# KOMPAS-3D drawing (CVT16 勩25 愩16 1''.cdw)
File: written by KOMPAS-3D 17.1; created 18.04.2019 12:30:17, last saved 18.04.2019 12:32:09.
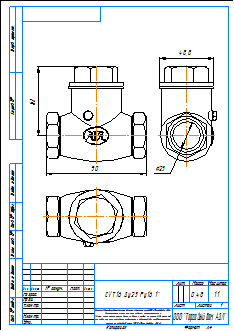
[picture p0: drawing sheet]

Sheet 1: A4, portrait

Title block, sheet 1: name: CVT16 Ду25 Ру16 1''; material: Внимание! Данный продукт является объектом авторского права ООО «Торговый Дом АДЛ». / Запрещается изменение, копирование, распространение / (в том числе путем копирования на другие сайты и ресурсы в Интернете) / или любое иное использование информации и объектов без предварительного / согласия правообладателя (ООО «Торговый Дом АДЛ»).; mass: 0,48; sheets: 1; organisation: ООО "Торговый дом АДЛ"; sheet format: A4

Views: Вид 1, Проекционный вид 2, Проекционный вид 3
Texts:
  user
Dimensions and other numbers on the sheet: 90; 62; 48,8; 25; 1:1; 1; 0,48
